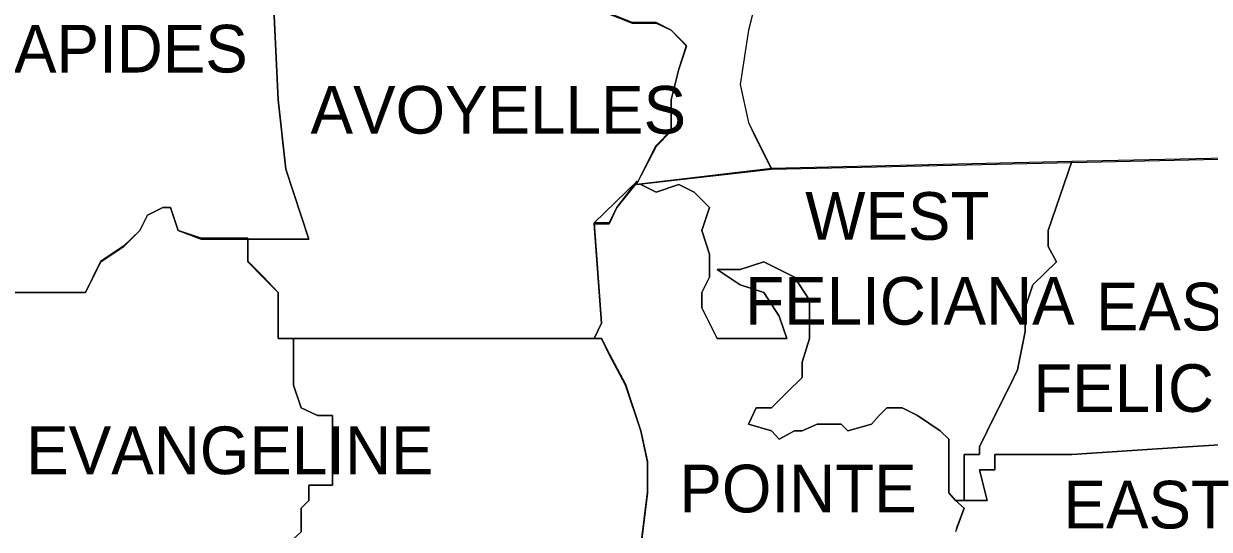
# Model space of a CAD drawing. Extents: x 0.19 to 2.82, y 0.04 to 1.79.
# Drawn here: x 2.3204 to 2.4368, y 1.5443 to 1.594 of the extents above; entities that cross this region are included whole.
import ezdxf

# ---------------------------------------------------------------- set-up
doc = ezdxf.new("R2010")
doc.units = 0
for name, color, linetype in [('Dist03', 7, 'Continuous'), ('Dist08', 7, 'Continuous'), ('Dist58', 7, 'Continuous'), ('Dist61', 7, 'Continuous'), ('Standard Info', 7, 'Continuous')]:
    doc.layers.add(name, color=color, linetype=linetype)

msp = doc.modelspace()

# ---------------------------------------------------------------- linework, layer by layer
at = {"layer": 'Dist03'}
for points in [[(2.3469, 1.56308), (2.3454, 1.56308), (2.3454, 1.56758), (2.3439, 1.56917), (2.3424, 1.57067), (2.3424, 1.57292), (2.34015, 1.57292), (2.33782, 1.57292), (2.33557, 1.57367), (2.33482, 1.57592), (2.33407, 1.57592), (2.33257, 1.57517), (2.33182, 1.57367), (2.33024, 1.57217), (2.32799, 1.57067), (2.32649, 1.56758), (2.31899, 1.56758)], [(2.37715, 1.56308), (2.3469, 1.56308)], [(2.3829, 1.53617), (2.38099, 1.53892), (2.38099, 1.54267), (2.38165, 1.548), (2.38165, 1.551), (2.38099, 1.554), (2.37949, 1.55858), (2.3779, 1.56158), (2.37715, 1.56308)]]:
    msp.add_lwpolyline(points, dxfattribs=at)
at = {"layer": 'Dist08'}
for points in [[(2.38057, 1.57817), (2.38249, 1.582), (2.38399, 1.5835), (2.38399, 1.5865), (2.38474, 1.5895), (2.38549, 1.59183), (2.38399, 1.59333), (2.38249, 1.59408), (2.38015, 1.59408), (2.3764, 1.59558), (2.37415, 1.59783), (2.37349, 1.59875)], [(2.3764, 1.57442), (2.3779, 1.57442), (2.37865, 1.57592), (2.38065, 1.5785)], [(2.30232, 1.56758), (2.32649, 1.56758), (2.32799, 1.57067), (2.33024, 1.57217), (2.33182, 1.57367), (2.33257, 1.57517), (2.33407, 1.57592), (2.33482, 1.57592), (2.33557, 1.57367), (2.33782, 1.57292), (2.34015, 1.57292), (2.3424, 1.57292)], [(2.3764, 1.56308), (2.37715, 1.56458), (2.3764, 1.57442)], [(2.3424, 1.57292), (2.3424, 1.57067), (2.3439, 1.56917), (2.3454, 1.56758), (2.3454, 1.56308), (2.3764, 1.56308)]]:
    msp.add_lwpolyline(points, dxfattribs=at)
at = {"layer": 'Dist58'}
for points in [[(2.40882, 1.63942), (2.40665, 1.63567), (2.40515, 1.63192), (2.40515, 1.62808), (2.40215, 1.62508), (2.39982, 1.62058), (2.39982, 1.613), (2.39907, 1.61), (2.39757, 1.60692), (2.39682, 1.60467), (2.39457, 1.60092), (2.39307, 1.59942), (2.39157, 1.59333), (2.39074, 1.588), (2.39157, 1.58425), (2.39232, 1.58275), (2.39382, 1.57975)], [(2.38057, 1.57817), (2.38249, 1.582), (2.38399, 1.5835), (2.38399, 1.5865), (2.38474, 1.5895), (2.38549, 1.59183), (2.38399, 1.59333), (2.38249, 1.59408), (2.38015, 1.59408), (2.3764, 1.59558), (2.37415, 1.59783), (2.37349, 1.59875)], [(2.39382, 1.57975), (2.38057, 1.57817)]]:
    msp.add_lwpolyline(points, dxfattribs=at)
at = {"layer": 'Dist61'}
msp.add_line((2.3764, 1.57442), (2.38065, 1.5785), dxfattribs=at)
for points in [[(2.44915, 1.581), (2.42332, 1.58042)], [(2.39382, 1.57975), (2.38057, 1.57817)], [(2.42332, 1.58042), (2.39382, 1.57975)], [(2.38065, 1.5785), (2.37865, 1.57592), (2.3779, 1.57442), (2.3764, 1.57442)], [(2.38049, 1.57825), (2.37865, 1.57592), (2.3779, 1.57442), (2.3764, 1.57442)], [(2.3764, 1.57442), (2.37715, 1.56458), (2.3764, 1.56308)], [(2.37715, 1.56308), (2.3779, 1.56158), (2.37949, 1.55858), (2.38099, 1.554), (2.38165, 1.551), (2.38165, 1.548), (2.38099, 1.54267), (2.38099, 1.53892), (2.3829, 1.53617)]]:
    msp.add_lwpolyline(points, dxfattribs=at)
at = {"layer": 'Standard Info'}
for p, q in [((2.42332, 1.58042), (2.42332, 1.58033)), ((2.37715, 1.56308), (2.3764, 1.56308))]:
    msp.add_line(p, q, dxfattribs=at)
for points in [[(2.40882, 1.63942), (2.40665, 1.63567), (2.40515, 1.63183), (2.40515, 1.62808), (2.40215, 1.62508), (2.39982, 1.6205), (2.39982, 1.61292), (2.39907, 1.60992), (2.39757, 1.60692), (2.39682, 1.60458), (2.39457, 1.60083), (2.39307, 1.59933), (2.39157, 1.59333), (2.39074, 1.588), (2.39157, 1.58425), (2.39232, 1.58267), (2.39382, 1.57967)], [(2.35815, 1.605), (2.35374, 1.60233), (2.35224, 1.60158), (2.35074, 1.60158), (2.3499, 1.60158), (2.3484, 1.60392), (2.3469, 1.60392), (2.3454, 1.60233), (2.34465, 1.60233), (2.3454, 1.5865), (2.34615, 1.57967), (2.3484, 1.57283), (2.3424, 1.57283)], [(2.3424, 1.57283), (2.3484, 1.57283), (2.34615, 1.57967), (2.3454, 1.5865), (2.34465, 1.60233), (2.3454, 1.60233), (2.3469, 1.60392), (2.3484, 1.60392), (2.3499, 1.60158), (2.35074, 1.60158), (2.35224, 1.60158), (2.35374, 1.60233), (2.35815, 1.605)], [(2.35815, 1.605), (2.35982, 1.60392), (2.36132, 1.60158), (2.36207, 1.60008), (2.36357, 1.59858), (2.36432, 1.59708), (2.36582, 1.59633), (2.36732, 1.59783), (2.36657, 1.59933), (2.36807, 1.60083), (2.3719, 1.60083), (2.37415, 1.59783), (2.3764, 1.5955), (2.38015, 1.594), (2.38249, 1.594), (2.38399, 1.59333), (2.38549, 1.59175), (2.38474, 1.5895), (2.38399, 1.5865), (2.38399, 1.58342), (2.38249, 1.58192), (2.38065, 1.57833)], [(2.38057, 1.57817), (2.38249, 1.58192), (2.38399, 1.58342), (2.38399, 1.5865), (2.38474, 1.5895), (2.38549, 1.59175), (2.38399, 1.59333), (2.38249, 1.594), (2.38015, 1.594), (2.3764, 1.5955), (2.37415, 1.59783), (2.37349, 1.59867)], [(2.42332, 1.58033), (2.44915, 1.58092)], [(2.39382, 1.57967), (2.38057, 1.57817)], [(2.38057, 1.57817), (2.39382, 1.57967)], [(2.39382, 1.57967), (2.42332, 1.58033)], [(2.42332, 1.58042), (2.42099, 1.57367), (2.42099, 1.57208), (2.42182, 1.57058), (2.41949, 1.56833), (2.41874, 1.56608), (2.41874, 1.56375), (2.41799, 1.56), (2.41724, 1.5585), (2.41574, 1.5555), (2.41424, 1.55242), (2.41424, 1.55167), (2.41274, 1.55167), (2.41274, 1.54942), (2.41274, 1.54717)], [(2.41274, 1.54717), (2.41274, 1.54942), (2.41274, 1.55167), (2.41424, 1.55167), (2.41424, 1.55242), (2.41574, 1.5555), (2.41724, 1.5585), (2.41799, 1.56), (2.41874, 1.56375), (2.41874, 1.56608), (2.41949, 1.56833), (2.42182, 1.57058), (2.42099, 1.57208), (2.42099, 1.57367), (2.42332, 1.58042)], [(2.38065, 1.57842), (2.37865, 1.57592), (2.3779, 1.57433), (2.3764, 1.57433)], [(2.3764, 1.57433), (2.3779, 1.57433), (2.37865, 1.57592), (2.38049, 1.57825)], [(2.38774, 1.57133), (2.38699, 1.57367), (2.38774, 1.57592), (2.38624, 1.57742), (2.38474, 1.57817), (2.38249, 1.57742), (2.38099, 1.57817)], [(2.38099, 1.57817), (2.38249, 1.57742), (2.38474, 1.57817), (2.38624, 1.57742), (2.38774, 1.57592), (2.38699, 1.57367), (2.38774, 1.57133)], [(2.3424, 1.57283), (2.34015, 1.57283), (2.33782, 1.57283), (2.33557, 1.57367), (2.33482, 1.57592), (2.33407, 1.57592), (2.33257, 1.57517), (2.33182, 1.57367), (2.33024, 1.57208), (2.32799, 1.57058), (2.32649, 1.56758), (2.30232, 1.56758)], [(2.31899, 1.56758), (2.32649, 1.56758), (2.32799, 1.57058), (2.33024, 1.57208), (2.33182, 1.57367), (2.33257, 1.57517), (2.33407, 1.57592), (2.33482, 1.57592), (2.33557, 1.57367), (2.33782, 1.57283), (2.34015, 1.57283), (2.3424, 1.57283), (2.3424, 1.57058), (2.3439, 1.56908), (2.3454, 1.56758), (2.3454, 1.56308), (2.3469, 1.56308)], [(2.3764, 1.57433), (2.37715, 1.56458), (2.3764, 1.56308)], [(2.3764, 1.56308), (2.37715, 1.56458), (2.3764, 1.57433)], [(2.3764, 1.56308), (2.3454, 1.56308), (2.3454, 1.56758), (2.3439, 1.56908), (2.3424, 1.57058), (2.3424, 1.57283)], [(2.38849, 1.56983), (2.39074, 1.56833), (2.39307, 1.56758), (2.39457, 1.56525), (2.39532, 1.56308), (2.39382, 1.56308), (2.39007, 1.56308), (2.38849, 1.56308), (2.38774, 1.56458), (2.38699, 1.56608), (2.38699, 1.56758), (2.38774, 1.56908), (2.38774, 1.57133)], [(2.38774, 1.57133), (2.38774, 1.56908), (2.38699, 1.56758), (2.38699, 1.56608), (2.38774, 1.56458), (2.38849, 1.56308), (2.39007, 1.56308), (2.39382, 1.56308), (2.39532, 1.56308), (2.39457, 1.56525), (2.39307, 1.56758), (2.39074, 1.56833), (2.38849, 1.56983)], [(2.4119, 1.54717), (2.41124, 1.54792), (2.41124, 1.55017), (2.41124, 1.55317), (2.4104, 1.554), (2.40815, 1.5555), (2.40665, 1.55625), (2.40515, 1.55625), (2.4044, 1.5555), (2.40365, 1.55467), (2.40132, 1.554), (2.40065, 1.55467), (2.39832, 1.55467), (2.39682, 1.554), (2.39607, 1.554), (2.39457, 1.55317), (2.39382, 1.554), (2.39157, 1.55467), (2.39232, 1.55625), (2.39382, 1.55625), (2.39532, 1.55775), (2.39682, 1.55925), (2.39682, 1.56075), (2.39757, 1.56308), (2.39757, 1.56683), (2.39607, 1.56908), (2.39307, 1.57058), (2.39074, 1.56983), (2.38849, 1.56983)], [(2.38849, 1.56983), (2.39074, 1.56983), (2.39307, 1.57058), (2.39607, 1.56908), (2.39757, 1.56683), (2.39757, 1.56308), (2.39682, 1.56075), (2.39682, 1.55925), (2.39532, 1.55775), (2.39382, 1.55625), (2.39232, 1.55625), (2.39157, 1.55467), (2.39382, 1.554), (2.39457, 1.55317), (2.39607, 1.554), (2.39682, 1.554), (2.39832, 1.55467), (2.40065, 1.55467), (2.40132, 1.554), (2.40365, 1.55467), (2.4044, 1.5555), (2.40515, 1.55625), (2.40665, 1.55625), (2.40815, 1.5555), (2.4104, 1.554), (2.41124, 1.55317), (2.41124, 1.55017), (2.41124, 1.54792), (2.4119, 1.54717), (2.41274, 1.54642), (2.4119, 1.54408)], [(2.3469, 1.56308), (2.3469, 1.5585), (2.34765, 1.55625), (2.34924, 1.5555), (2.35074, 1.5555), (2.35074, 1.54867), (2.3484, 1.54867), (2.3484, 1.54717), (2.34765, 1.54642), (2.34765, 1.54408), (2.3469, 1.54342), (2.3469, 1.53958), (2.3439, 1.53958), (2.34315, 1.53733), (2.33107, 1.53733), (2.32874, 1.53583), (2.32874, 1.5335), (2.32649, 1.5335), (2.32724, 1.532)], [(2.32724, 1.532), (2.32649, 1.5335), (2.32874, 1.5335), (2.32874, 1.53583), (2.33107, 1.53733), (2.34315, 1.53733), (2.3439, 1.53958), (2.3469, 1.53958), (2.3469, 1.54342), (2.34765, 1.54408), (2.34765, 1.54642), (2.3484, 1.54717), (2.3484, 1.54867), (2.35074, 1.54867), (2.35074, 1.5555), (2.34924, 1.5555), (2.34765, 1.55625), (2.3469, 1.5585), (2.3469, 1.56308)], [(2.3469, 1.56308), (2.37715, 1.56308)], [(2.37715, 1.56308), (2.3779, 1.5615), (2.37949, 1.5585), (2.38099, 1.554), (2.38165, 1.55092), (2.38165, 1.54792), (2.38099, 1.54258), (2.38099, 1.53883), (2.3829, 1.53617)], [(2.38474, 1.53433), (2.38324, 1.53583), (2.38099, 1.53883), (2.38099, 1.54258), (2.38165, 1.54792), (2.38165, 1.55092), (2.38099, 1.554), (2.37949, 1.5585), (2.3779, 1.5615), (2.37715, 1.56308)], [(2.4119, 1.54717), (2.41499, 1.54717), (2.41424, 1.55017), (2.41574, 1.55017), (2.41574, 1.55167), (2.42332, 1.55167), (2.43465, 1.55242), (2.44674, 1.55317)], [(2.44674, 1.55317), (2.43465, 1.55242), (2.42332, 1.55167), (2.41574, 1.55167), (2.41574, 1.55017), (2.41424, 1.55017), (2.41499, 1.54717), (2.41274, 1.54717)], [(2.41274, 1.54717), (2.4119, 1.54717)], [(2.41199, 1.54442), (2.41274, 1.54642), (2.4119, 1.54717)]]:
    msp.add_lwpolyline(points, dxfattribs=at)

# ---------------------------------------------------------------- texts
for s, p in [('RAPIDES', (2.31494, 1.58917)), ('AVOYELLES', (2.34857, 1.58317)), ('WEST', (2.39714, 1.57275)), ('FELICIANA', (2.39125, 1.56442)), ('EAST', (2.42568, 1.56386)), ('FELICIANA', (2.41953, 1.55586)), ('EVANGELINE', (2.32066, 1.54975)), ('POINTE', (2.38478, 1.546)), ('EAST', (2.42249, 1.54442))]:
    msp.add_text(s, height=0.004679, dxfattribs=at).set_placement(p)

doc.saveas('drawing.dxf')
